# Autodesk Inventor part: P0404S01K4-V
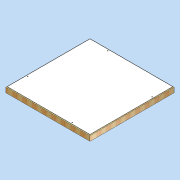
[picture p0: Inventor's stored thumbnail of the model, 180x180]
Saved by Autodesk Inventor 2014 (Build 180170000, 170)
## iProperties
Created: 2011-04
Part Number: P0404S01K4-V
Document SubType Name: Modeling
Designer: david.appleford
Density: 0.198834 g/cm^3
Description: 1w x 1w 01 Panel - 4 Locks
Cost Center: £83.00
Mass: 21000 g
Surface Area: 30231.7 cm^2
Volume: 105616 cm^3
Material: Generic
Appearance: Wood (Pine)
Justset: False
Title: 1w x 1w 01 Panel - 4 Locks
Author: david.appleford
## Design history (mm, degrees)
sketch "Sketch1"
  geometry: L1 (0, 0)-(1220, 0); L2 (1220, 0)-(1220, 1220); L3 (1220, 1220)-(0, 1220); L4 (0, 1220)-(0, 0); L5 (34, 1186)-(1186, 1186); L6 (1186, 1186)-(1186, 34); L7 (1186, 34)-(34, 34); L8 (34, 34)-(34, 1186)
  constraints: 16 end point, 4 parallel, 2 perpendicular, 1 horizontal, 3 other
  dimensions: "d0" = 1220 distance between parallel lines of L2 L4 (= w); "d1" = 1220 distance between parallel lines of L1 L3 (= w); "d2" = 34 distance between parallel lines of L5 L3 (= 0.5 x t)
extrude "Extrusion1" new body sketch "Sketch1" distance "d3" = 68 (= t); taper "d4" = 0 deg
sketch "Sketch2"
  geometry: L1 (1186, 1186)-(1186, 34) reference; L2 (34, 1186)-(1186, 1186) reference; L3 (34, 34)-(34, 1186) reference; L4 (1186, 34)-(34, 34) reference; L5 (1176, 1176)-(1176, 44); L6 (1176, 44)-(44, 44); L7 (44, 44)-(44, 1176); L8 (44, 1176)-(1176, 1176); 1 further point
  constraints: 8 end point, 3 other
  dimensions: "d5" = 10 distance between parallel lines of L8 L2
extrude "Extrusion2" join sketch "Sketch2" distance "d6" = 6 (= sw); taper "d7" = 0 deg
sketch "Sketch3"
  geometry: L1 (-44, 1176)-(-1176, 1176) reference; L2 (-1176, 1176)-(-1176, 44) reference; L3 (-44, 44)-(-44, 1176) reference; L4 (-1176, 44)-(-44, 44) reference; 1 further point
extrude "Extrusion3" join sketch "Sketch3" distance "d8" = 6 (= sw); taper "d9" = 0 deg
sketch "Sketch4"
  geometry: L1 (34, 1186)-(1186, 1186) reference; L2 (1186, 1186)-(1186, 34) reference; L3 (1186, 34)-(34, 34) reference; L4 (34, 34)-(34, 1186) reference; 5 further points
  dimensions: "d10" = 28 distance from line of point (305, 1158) L1 (= k); "d12" = 28 distance from line of L3 point (915, 62) (= k); "d13" = 28 distance from line of point (62, 305) L4 (= k); "d14" = 305 horizontal distance of point (305, 1158) point (0, 0) (= 0.25 x w); "d15" = 610 horizontal distance of point (915, 62) point (305, 1158) (= 0.5 x w); "d16" = 305 vertical distance of point (62, 305) point (0, 0) (= 0.25 x w); "d19" = 610 vertical distance of point (1158, 915) point (62, 305) (= 0.5 x w)
hole "Hole1" sketch "Sketch4" at (305, 1158), (62, 305), (1158, 915), (915, 62) diameter "d22" = 12 (= hd); stored, may be unused: countersink angle "d26" = 90 deg, drill point angle "d28" = 118 deg; dims "d23" = 6, "d24" = 4, "d25" = 2, "d27" = 8
body "Solid1"
node "Projected Loop1"
other parameters: "w" = 1220 [user parameter; used in 6 equation terms], "t" = 68 [user parameter; used in 2 equation terms], "e" = 16 [user parameter], "sw" = 6 [user parameter; used in 2 equation terms], "sc" = 9 [user parameter], "sf" = 12 [user parameter], "k" = 28 [user parameter; used in 3 equation terms], "hd" = 12 [user parameter; used in 1 equation term]
